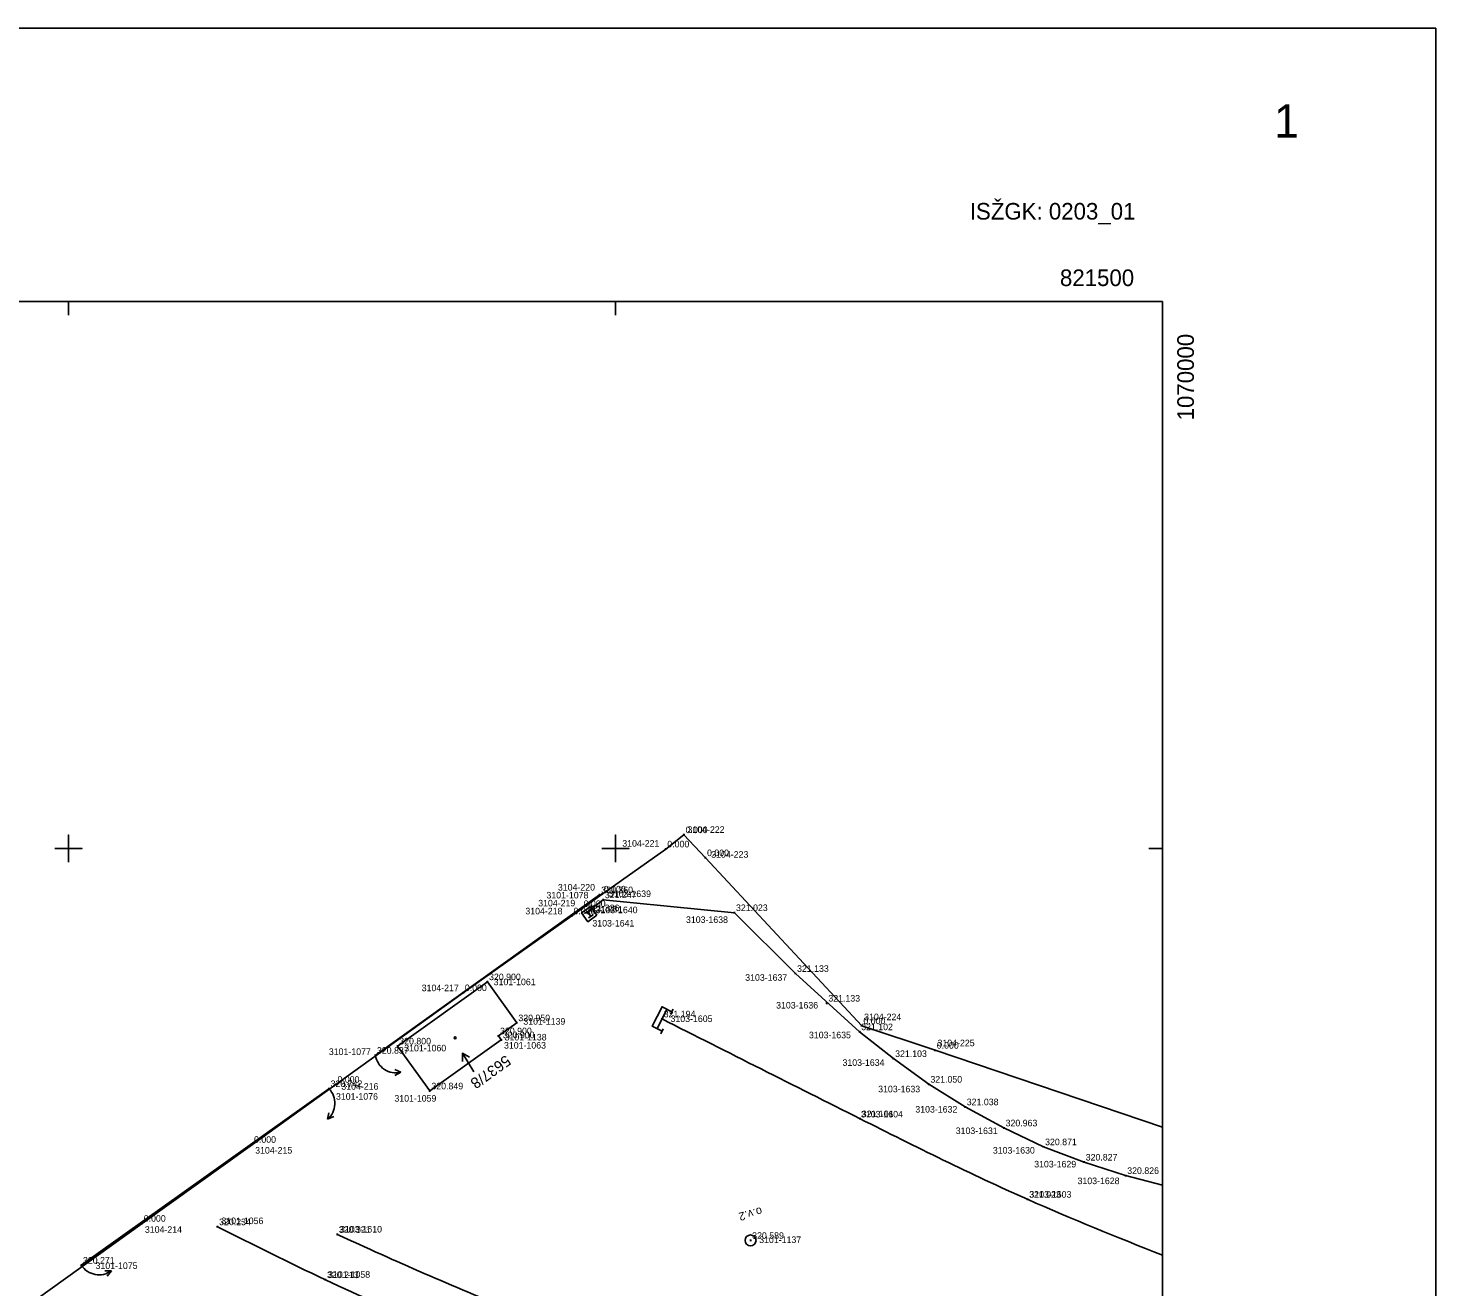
# Model space of a CAD drawing. Extents: x -821875 to -821475, y -1070280 to -1069975.
# Drawn here: x -821603.7 to -821475, y -1070090.1 to -1069975 of the extents above; entities that cross this region are included whole.
import ezdxf

# ---------------------------------------------------------------- set-up
doc = ezdxf.new("R2010")
doc.units = 0
for name, color, linetype in [('Vrstva 1', 7, 'Continuous'), ('Vrstva 15', 7, 'Continuous'), ('Vrstva 17', 7, 'Continuous'), ('Vrstva 23', 7, 'Continuous'), ('Vrstva 25', 7, 'Continuous'), ('Vrstva 3', 7, 'Continuous'), ('Vrstva 33', 7, 'Continuous'), ('Vrstva 52', 7, 'Continuous'), ('Vrstva 53', 7, 'Continuous'), ('Vrstva 54', 7, 'Continuous'), ('Vrstva 57', 7, 'Continuous'), ('Vrstva 59', 7, 'Continuous'), ('Vrstva 60', 7, 'Continuous'), ('Vrstva 61', 7, 'Continuous')]:
    doc.layers.add(name, color=color, linetype=linetype)

# ---------------------------------------------------------------- blocks, each defined once
blk = doc.blocks.new('BOD')
at = {"layer": 'Vrstva 3'}
for p, q in [((-0.15, 0), (0.15, 0)), ((0, -0.15), (0, 0.15))]:
    blk.add_line(p, q, dxfattribs=at)

msp = doc.modelspace()

# ---------------------------------------------------------------- linework, layer by layer
at = {"layer": 'Vrstva 1'}
for points in [[(-821475, -1069975), (-821875, -1069975), (-821875, -1070275), (-821475, -1070275)], [(-821500, -1070000), (-821850, -1070000), (-821850, -1070250), (-821500, -1070250)], [(-821500, -1070000), (-821850, -1070000), (-821850, -1070250), (-821500, -1070250)]]:
    msp.add_lwpolyline(points, close=True, dxfattribs=at)
for points in [[(-821601.25, -1070000), (-821600, -1070000)], [(-821600, -1070000), (-821598.75, -1070000), (-821600, -1070000)], [(-821600, -1070000), (-821600, -1070001.25)], [(-821551.25, -1070000), (-821550, -1070000)], [(-821550, -1070000), (-821548.75, -1070000), (-821550, -1070000)], [(-821550, -1070000), (-821550, -1070001.25)], [(-821501.25, -1070000), (-821500, -1070000)], [(-821500, -1070000), (-821500, -1070001.25)], [(-821601.25, -1070050), (-821600, -1070050), (-821600, -1070048.75), (-821600, -1070050), (-821598.75, -1070050), (-821600, -1070050), (-821600, -1070051.25)], [(-821551.25, -1070050), (-821550, -1070050), (-821550, -1070048.75), (-821550, -1070050), (-821548.75, -1070050), (-821550, -1070050), (-821550, -1070051.25)], [(-821500, -1070050), (-821500, -1070048.75), (-821500, -1070050)], [(-821501.25, -1070050), (-821500, -1070050)], [(-821500, -1070050), (-821500, -1070051.25)]]:
    msp.add_lwpolyline(points, dxfattribs=at)
for points in [[(-821500, -1070087.177), (-821512.332, -1070082.065), (-821527.629, -1070074.701), (-821545.734, -1070065.58)], [(-821500, -1070107.532), (-821514.414, -1070107.377), (-821530.282, -1070105.08), (-821548.548, -1070100.3), (-821566.929, -1070093.631), (-821576.512, -1070089.417), (-821586.373, -1070084.578)], [(-821500, -1070104.505), (-821504.552, -1070104.218), (-821524.6, -1070101.851), (-821543.27, -1070097.565), (-821559.418, -1070092.193), (-821575.427, -1070085.277)]]:
    msp.add_spline(points, degree=3, dxfattribs=at)
at = {"layer": 'Vrstva 15'}
for p, q in [((-821546.184, -1070066.473), (-821545.284, -1070064.687)), ((-821544.95, -1070065.135), (-821544.725, -1070064.689)), ((-821545.849, -1070066.921), (-821545.625, -1070066.475))]:
    msp.add_line(p, q, dxfattribs=at)
msp.add_lwpolyline([(-821544.838, -1070064.912), (-821545.731, -1070064.462), (-821546.63, -1070066.248), (-821545.737, -1070066.698)], dxfattribs=at)
at = {"layer": 'Vrstva 17'}
for p, q in [((-821571.944, -1070068.906), (-821551.44, -1070054.228)), ((-821598.818, -1070088.088), (-821576.179, -1070071.952))]:
    msp.add_line(p, q, dxfattribs=at)
for points in [[(-821551.114, -1070054.684), (-821552.682, -1070055.874)], [(-821500, -1070080.783), (-821503.36, -1070079.893), (-821507.156, -1070078.666), (-821510.868, -1070077.267), (-821514.478, -1070075.542), (-821518.028, -1070073.613), (-821521.353, -1070071.547), (-821524.578, -1070069.201), (-821527.681, -1070066.752), (-821533.542, -1070061.421), (-821539.125, -1070055.86), (-821551.114, -1070054.684)]]:
    msp.add_lwpolyline(points, dxfattribs=at)
at = {"layer": 'Vrstva 23'}
for p, q in [((-821569.618, -1070070.452), (-821570.174, -1070070.201)), ((-821570.171, -1070070.76), (-821569.618, -1070070.452)), ((-821569.618, -1070070.452), (-821570.171, -1070070.76)), ((-821576.312, -1070074.742), (-821576.185, -1070074.145)), ((-821575.737, -1070074.48), (-821576.312, -1070074.742)), ((-821576.312, -1070074.742), (-821575.737, -1070074.48)), ((-821596.072, -1070088.601), (-821596.682, -1070088.587)), ((-821596.46, -1070089.1), (-821596.072, -1070088.601)), ((-821596.072, -1070088.601), (-821596.46, -1070089.1))]:
    msp.add_line(p, q, dxfattribs=at)
msp.add_lwpolyline([(-821569.903, -1070068.055), (-821566.965, -1070072.161), (-821560.436, -1070067.487), (-821560.693, -1070067.126), (-821559.017, -1070065.928), (-821561.696, -1070062.18), (-821569.903, -1070068.055)], dxfattribs=at)
for centre, start, end in [((-821570.054, -1070068.586), 189.62302, 283.1429), ((-821577.558, -1070073.284), 310.50591, 44.02579), ((-821597.204, -1070087.053), 212.66413, 306.18401)]:
    msp.add_arc(centre, 1.917, start, end, dxfattribs=at)
at = {"layer": 'Vrstva 25'}
msp.add_circle((-821537.645, -1070085.825), 0.5, dxfattribs=at)
at = {"layer": 'Vrstva 33'}
for p, q in [((-821552.248, -1070056.191), (-821552.538, -1070055.785)), ((-821552.044, -1070056.046), (-821552.451, -1070056.337))]:
    msp.add_line(p, q, dxfattribs=at)
msp.add_lwpolyline([(-821551.696, -1070056.103), (-821552.508, -1070056.685), (-821553.09, -1070055.873), (-821552.278, -1070055.291), (-821551.696, -1070056.103)], dxfattribs=at)
at = {"layer": 'Vrstva 52'}
msp.add_lwpolyline([(-821569.903, -1070068.055), (-821561.696, -1070062.18), (-821559.017, -1070065.928), (-821560.693, -1070067.126), (-821560.436, -1070067.487), (-821566.965, -1070072.161), (-821569.903, -1070068.055)], dxfattribs=at)
at = {"layer": 'Vrstva 53'}
for points in [[(-821551.21, -1070054.16), (-821545.4, -1070050.04), (-821543.73, -1070048.74), (-821541.77, -1070050.84), (-821527.48, -1070066.2), (-821520.77, -1070068.44), (-821500, -1070075.458)], [(-821734.56, -1070151.86), (-821659.89, -1070131.96), (-821621.57, -1070104.56), (-821609.88, -1070096.2), (-821593.26, -1070084.26), (-821583.18, -1070077.05), (-821575.55, -1070071.56), (-821563.91, -1070063.18), (-821553.98, -1070056.16), (-821553.05, -1070055.49), (-821551.21, -1070054.16)]]:
    msp.add_lwpolyline(points, dxfattribs=at)
at = {"layer": 'Vrstva 54'}
msp.add_line((-821563.969, -1070069.458), (-821563.984, -1070068.708), dxfattribs=at)
msp.add_lwpolyline([(-821562.95, -1070070.42), (-821563.984, -1070068.708), (-821563.327, -1070069.071)], dxfattribs=at)
at = {"layer": 'Vrstva 59'}
msp.add_circle((-821564.649, -1070067.306), 0.0873, dxfattribs=at)

# ---------------------------------------------------------------- block references
at = {"layer": 'Vrstva 60', "xscale": 0.5, "yscale": 0.5}
for p in [(-821543.73, -1070048.74), (-821545.4, -1070050.04), (-821541.77, -1070050.84), (-821551.44, -1070054.228), (-821551.21, -1070054.16), (-821551.114, -1070054.684), (-821553.98, -1070056.16), (-821553.05, -1070055.49), (-821552.682, -1070055.874), (-821552.393, -1070055.988), (-821539.125, -1070055.86), (-821533.542, -1070061.421), (-821561.696, -1070062.18), (-821563.91, -1070063.18), (-821530.681, -1070064.136), (-821559.017, -1070065.928), (-821545.734, -1070065.58), (-821527.48, -1070066.2), (-821560.693, -1070067.126), (-821560.436, -1070067.487), (-821527.681, -1070066.752), (-821571.944, -1070068.906), (-821569.903, -1070068.055), (-821520.77, -1070068.44), (-821524.578, -1070069.201), (-821575.55, -1070071.56), (-821521.353, -1070071.547), (-821576.179, -1070071.952), (-821566.965, -1070072.161), (-821518.028, -1070073.613), (-821527.629, -1070074.701), (-821514.478, -1070075.542), (-821583.18, -1070077.05), (-821510.868, -1070077.267), (-821507.156, -1070078.666), (-821503.36, -1070079.893), (-821512.332, -1070082.065), (-821593.26, -1070084.26), (-821586.373, -1070084.578), (-821575.427, -1070085.277), (-821537.645, -1070085.825), (-821598.818, -1070088.088), (-821576.512, -1070089.417)]:
    msp.add_blockref('BOD', p, dxfattribs=at)

# ---------------------------------------------------------------- texts
at = {"layer": 'Vrstva 1'}
for s, height, p in [('  1', 3.04, (-821492.037, -1069985)), ('ISŽGK: 0203_01', 1.52, (-821517.603, -1069992.5)), ('821500', 1.52, (-821509.362, -1069998.578))]:
    msp.add_text(s, height=height, dxfattribs=at).set_placement(p)
msp.add_text('1070000', height=1.52, rotation=90, dxfattribs=at).set_placement((-821497.116, -1070010.857))
at = {"layer": 'Vrstva 25'}
msp.add_text('o.v.2', height=0.75, rotation=194.97321, dxfattribs=at).set_placement((-821536.687, -1070082.763))
at = {"layer": 'Vrstva 57'}
msp.add_text('5637/8', height=1, rotation=215.59823, dxfattribs=at).set_placement((-821560.022, -1070068.834))
at = {"layer": 'Vrstva 60'}
for s, p in [('3104-222', (-821543.406, -1070048.562)), ('3104-221', (-821549.369, -1070049.827)), ('3104-223', (-821541.236, -1070050.837)), ('3104-220', (-821555.253, -1070053.839)), ('3104-219', (-821557.057, -1070055.288)), ('3101-1078', (-821556.302, -1070054.56)), ('3103-1639', (-821550.584, -1070054.434)), ('3104-218', (-821558.227, -1070056.017)), ('3103-1640', (-821551.808, -1070055.908)), ('3103-1638', (-821543.546, -1070056.798)), ('3103-1641', (-821552.101, -1070057.126)), ('3104-217', (-821567.703, -1070063.037)), ('3101-1061', (-821561.127, -1070062.491)), ('3103-1637', (-821538.131, -1070062.085)), ('3103-1636', (-821535.306, -1070064.622)), ('3104-224', (-821527.259, -1070065.689)), ('3101-1139', (-821558.414, -1070066.099)), ('3103-1605', (-821544.956, -1070065.856)), ('3101-1063', (-821560.181, -1070068.286)), ('3101-1138', (-821560.124, -1070067.542)), ('3103-1635', (-821532.306, -1070067.345)), ('3104-225', (-821520.549, -1070068.071)), ('3101-1077', (-821576.191, -1070068.868)), ('3101-1060', (-821569.3, -1070068.54)), ('3103-1634', (-821529.238, -1070069.865)), ('3104-216', (-821575.051, -1070072.045)), ('3101-1076', (-821575.541, -1070072.96)), ('3101-1059', (-821570.2, -1070073.134)), ('3103-1633', (-821525.978, -1070072.282)), ('3103-1604', (-821527.551, -1070074.581)), ('3103-1632', (-821522.581, -1070074.134)), ('3103-1631', (-821518.889, -1070076.099)), ('3104-215', (-821582.926, -1070077.884)), ('3103-1630', (-821515.493, -1070077.884)), ('3103-1629', (-821511.715, -1070079.149)), ('3103-1628', (-821507.752, -1070080.677)), ('3103-1603', (-821512.149, -1070081.915)), ('3104-214', (-821593.006, -1070085.128)), ('3101-1056', (-821586.013, -1070084.331)), ('3103-1610', (-821575.172, -1070085.099)), ('3101-1137', (-821536.853, -1070086.061)), ('3101-1075', (-821597.516, -1070088.433)), ('3101-1058', (-821576.257, -1070089.239))]:
    msp.add_text(s, height=0.6, dxfattribs=at).set_placement(p)
at = {"layer": 'Vrstva 61'}
for s, p in [('0.000', (-821543.58, -1070048.59)), ('0.000', (-821545.25, -1070049.89)), ('0.000', (-821541.62, -1070050.69)), ('321.360', (-821551.29, -1070054.078)), ('0.000', (-821551.06, -1070054.01)), ('0.000', (-821552.9, -1070055.34)), ('321.247', (-821550.964, -1070054.534)), ('0.000', (-821553.83, -1070056.01)), ('321.336', (-821552.532, -1070055.724)), ('321.231', (-821552.243, -1070055.838)), ('321.023', (-821538.975, -1070055.71)), ('321.133', (-821533.392, -1070061.271)), ('0.000', (-821563.76, -1070063.03)), ('320.900', (-821561.546, -1070062.03)), ('321.133', (-821530.531, -1070063.986)), ('320.950', (-821558.867, -1070065.778)), ('321.194', (-821545.584, -1070065.43)), ('320.900', (-821560.543, -1070066.976)), ('321.102', (-821527.531, -1070066.602)), ('0.000', (-821527.33, -1070066.05)), ('320.800', (-821569.753, -1070067.905)), ('320.900', (-821560.286, -1070067.337)), ('0.000', (-821520.62, -1070068.29)), ('320.837', (-821571.794, -1070068.756)), ('321.103', (-821524.428, -1070069.051)), ('320.742', (-821576.029, -1070071.802)), ('0.000', (-821575.4, -1070071.41)), ('320.849', (-821566.815, -1070072.011)), ('321.050', (-821521.203, -1070071.397)), ('321.038', (-821517.878, -1070073.463)), ('321.101', (-821527.479, -1070074.551)), ('320.963', (-821514.328, -1070075.392)), ('0.000', (-821583.03, -1070076.9)), ('320.871', (-821510.718, -1070077.117)), ('320.827', (-821507.006, -1070078.516)), ('320.826', (-821503.21, -1070079.743)), ('321.023', (-821512.182, -1070081.915)), ('0.000', (-821593.11, -1070084.11)), ('320.234', (-821586.223, -1070084.428)), ('320.321', (-821575.277, -1070085.127)), ('320.589', (-821537.495, -1070085.675)), ('320.271', (-821598.668, -1070087.938)), ('320.213', (-821576.362, -1070089.267))]:
    msp.add_text(s, height=0.6, dxfattribs=at).set_placement(p)

doc.saveas('drawing.dxf')
